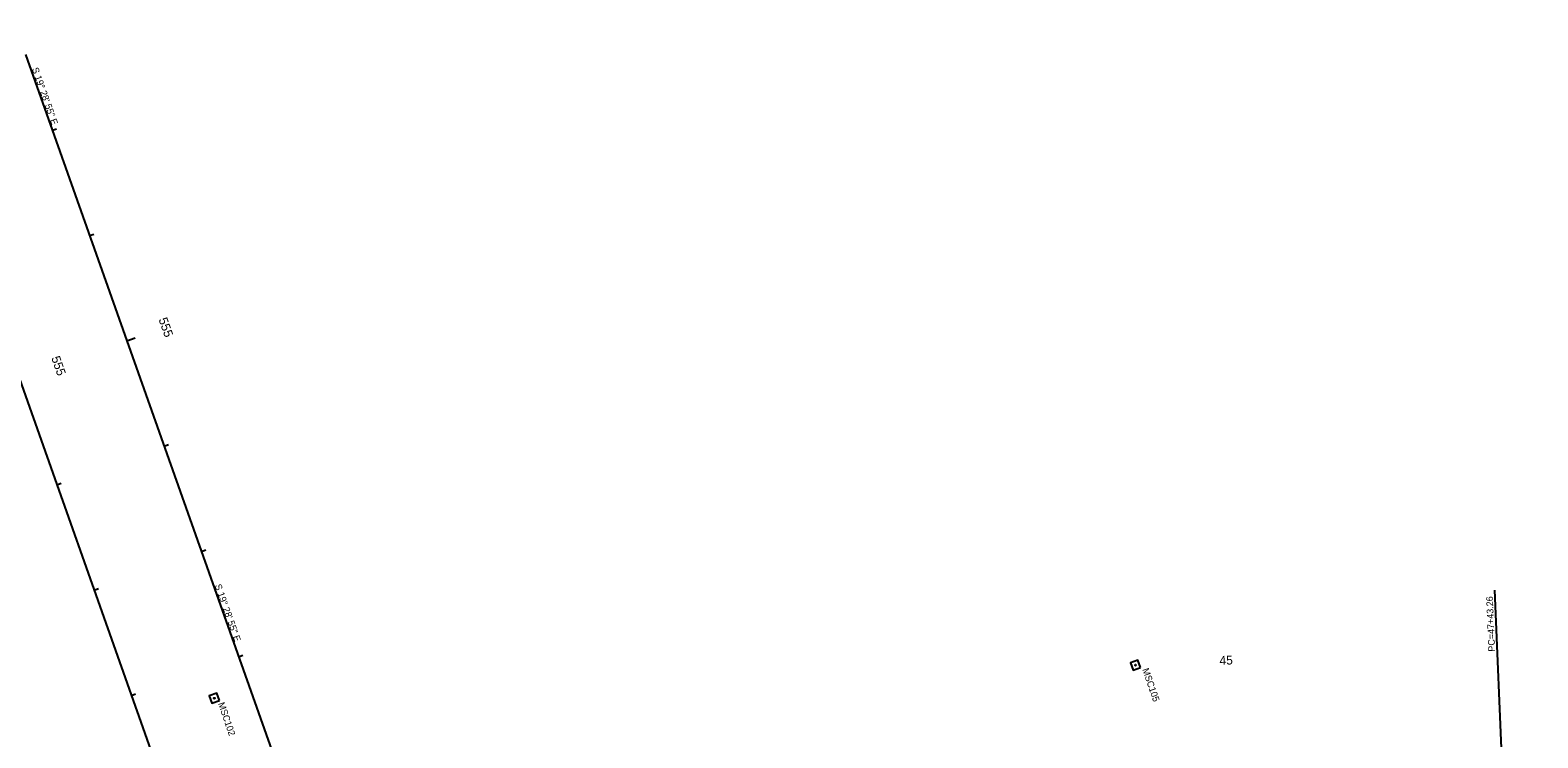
# Model space of a CAD drawing. Extents: x 2004390 to 2008791, y 1133870 to 1140084.
# Drawn here: x 2005751 to 2007099, y 1137320 to 1137953 of the extents above; entities that cross this region are included whole.
import ezdxf

# ---------------------------------------------------------------- set-up
doc = ezdxf.new("R2010")
doc.units = 0
for name, color, linetype in [('RD_HC_Cl', 7, 'Continuous'), ('RD_HC_CL_Rel', 7, 'Continuous'), ('RD_HC_Data', 7, 'Continuous'), ('RD_HC_Data_Rel', 7, 'Continuous'), ('RD_HC_Data_Tic', 7, 'Continuous'), ('RD_HC_Survey', 7, 'Continuous'), ('RD_HC_Survey_txCode', 7, 'Continuous'), ('RD_HC_TX_Rel_Sta50', 7, 'Continuous'), ('RD_HC_TX_Sta50', 7, 'Continuous')]:
    doc.layers.add(name, color=color, linetype=linetype)

msp = doc.modelspace()

# ---------------------------------------------------------------- linework, layer by layer
at = {"layer": 'RD_HC_Cl'}
for p, q in [((2005036.1, 1139633.5), (2007075.2, 1133869.8)), ((2005746.4, 1137931.6), (2006120.3, 1136874.9))]:
    msp.add_line(p, q, dxfattribs=at)
at = {"layer": 'RD_HC_CL_Rel'}
msp.add_arc((2007047.3, 1137772.5), 485, 272.4547, 353.919, dxfattribs=at)
at = {"layer": 'RD_HC_Data_Rel'}
msp.add_line((2007068, 1137287.9), (2007061, 1137452), dxfattribs=at)
at = {"layer": 'RD_HC_Data_Tic'}
for p, q in [((2005770.4, 1137863.9), (2005774.2, 1137865.2)), ((2005803.7, 1137769.6), (2005807.5, 1137770.9)), ((2005837.1, 1137675.3), (2005844.6, 1137678)), ((2005870.4, 1137581), (2005874.2, 1137582.4)), ((2005774.5, 1137546.5), (2005778.2, 1137547.8)), ((2005903.8, 1137486.8), (2005907.6, 1137488.1)), ((2005807.8, 1137452.2), (2005811.6, 1137453.5)), ((2005937.1, 1137392.5), (2005940.9, 1137393.8)), ((2005841.2, 1137357.9), (2005844.9, 1137359.3))]:
    msp.add_line(p, q, dxfattribs=at)
at = {"layer": 'RD_HC_Survey'}
for points in [[(2006744.1, 1137382.7), (2006741.7, 1137389.4), (2006735.1, 1137387.1), (2006737.4, 1137380.4)], [(2005919.9, 1137353.2), (2005917.5, 1137359.8), (2005910.8, 1137357.5), (2005913.2, 1137350.8)]]:
    msp.add_lwpolyline(points, close=True, dxfattribs=at)
for centre in [(2006739.6, 1137384.9), (2005915.3, 1137355.3)]:
    msp.add_circle(centre, 0.5, dxfattribs=at)

# ---------------------------------------------------------------- texts
at = {"layer": 'RD_HC_Data'}
for p in [(2005752, 1137918.8), (2005915.6, 1137456.3)]:
    msp.add_text('S 19%%d 28\' 55" E', height=6, rotation=289.482, dxfattribs=at).set_placement(p)
at = {"layer": 'RD_HC_Data_Rel'}
msp.add_text('PC=47+43.26', height=6, rotation=92.4547, dxfattribs=at).set_placement((2007061.3, 1137397.2))
at = {"layer": 'RD_HC_Survey_txCode'}
for s, p in [('MSC105', (2006745.5, 1137381.1)), ('MSC102', (2005918.6, 1137350.6))]:
    msp.add_text(s, height=6, rotation=288.8025, dxfattribs=at).set_placement(p)
at = {"layer": 'RD_HC_TX_Rel_Sta50'}
msp.add_text('45', height=8, rotation=2.4547, dxfattribs=at).set_placement((2006814.8, 1137385.1))
at = {"layer": 'RD_HC_TX_Sta50'}
for p in [(2005865.3, 1137694.5), (2005769.3, 1137660)]:
    msp.add_text('555', height=8, rotation=289.482, dxfattribs=at).set_placement(p)

doc.saveas('drawing.dxf')
